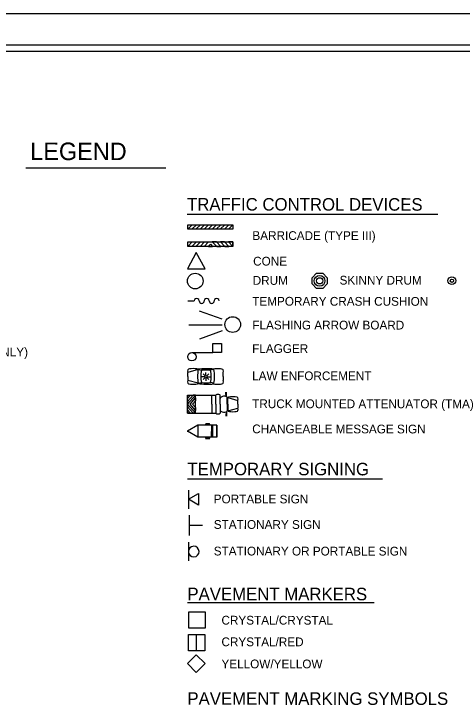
# Model space of a CAD drawing. Extents: x 0 to 1868, y 0 to 1100.
# Drawn here: x 1130 to 1488, y 547 to 1100 of the extents above; entities that cross this region are included whole.
import ezdxf

# ---------------------------------------------------------------- set-up
doc = ezdxf.new("R2010")
doc.units = 0
for name, color, linetype in [('Exist Utilities Sanitary Sewer Test Hole SUE LOS A CELL', 7, 'Continuous'), ('Exist Utilities Water Test Hole SUE LOS A CELL', 7, 'Continuous'), ('P_RDY_ROW_Permanent_Easement_CELL', 7, 'Continuous')]:
    doc.layers.add(name, color=color, linetype=linetype)

msp = doc.modelspace()

# ---------------------------------------------------------------- linework, layer by layer
at = {"layer": 'Exist Utilities Sanitary Sewer Test Hole SUE LOS A CELL'}
msp.add_lwpolyline([(0, 0), (1688, 0), (1688, 1100), (0, 1100)], close=True, dxfattribs=at)
at = {"layer": 'Exist Utilities Water Test Hole SUE LOS A CELL'}
msp.add_lwpolyline([(1275.53, 573.87), (1282.64, 580.98), (1275.53, 588.09), (1268.41, 580.98)], close=True, dxfattribs=at)
msp.add_lwpolyline([(1275.53, 573.87), (1282.64, 580.98), (1275.53, 588.09), (1268.41, 580.98)], close=True, dxfattribs=at)
at = {"layer": 'P_RDY_ROW_Permanent_Easement_CELL'}
for p, q in [((1652.71, 1075), (173.28, 1075)), ((1652.71, 1070), (740.76, 1070)), ((1139.64, 977.12), (1251.2, 977.12)), ((1268.12, 940.04), (1468.35, 940.04)), ((1268.79, 927.97), (1268.79, 931.58)), ((1268.79, 931.58), (1272.33, 931.58)), ((1272.33, 931.58), (1268.79, 927.97)), ((1268.79, 931.58), (1304.77, 931.58)), ((1268.79, 928.03), (1268.79, 931.58)), ((1272.03, 927.97), (1275.57, 931.58)), ((1278.81, 931.58), (1275.27, 927.97)), ((1275.57, 931.58), (1278.81, 931.58)), ((1278.5, 927.97), (1282.05, 931.58)), ((1285.29, 931.58), (1281.74, 927.97)), ((1282.05, 931.58), (1285.29, 931.58)), ((1284.98, 927.97), (1288.52, 931.58)), ((1291.76, 931.58), (1288.22, 927.97)), ((1288.52, 931.58), (1291.76, 931.58)), ((1291.45, 927.97), (1295.06, 931.58)), ((1298.3, 931.58), (1294.69, 927.97)), ((1295.06, 931.58), (1298.3, 931.58)), ((1297.93, 927.97), (1301.53, 931.58)), ((1304.77, 931.58), (1301.17, 927.97)), ((1301.53, 931.58), (1304.77, 931.58)), ((1304.77, 931.58), (1304.77, 928.03)), ((1304.77, 928.03), (1268.79, 928.03)), ((1275.27, 927.97), (1272.03, 927.97)), ((1281.74, 927.97), (1278.5, 927.97)), ((1288.22, 927.97), (1284.98, 927.97)), ((1294.69, 927.97), (1291.45, 927.97)), ((1301.17, 927.97), (1297.93, 927.97)), ((1268.8, 914.26), (1268.8, 917.86)), ((1268.8, 917.86), (1272.34, 917.86)), ((1272.34, 917.86), (1268.8, 914.26)), ((1268.8, 917.86), (1304.77, 917.86)), ((1268.8, 914.26), (1268.8, 917.86)), ((1304.77, 914.26), (1268.8, 914.26)), ((1272.03, 914.26), (1275.58, 917.86)), ((1275.27, 914.26), (1272.03, 914.26)), ((1278.81, 917.86), (1275.27, 914.26)), ((1275.58, 917.86), (1278.81, 917.86)), ((1278.51, 914.26), (1282.05, 917.86)), ((1281.75, 914.26), (1278.51, 914.26)), ((1285.29, 917.86), (1281.75, 914.26)), ((1282.05, 917.86), (1285.29, 917.86)), ((1284.98, 914.26), (1286.78, 916.09)), ((1288.22, 914.26), (1284.98, 914.26)), ((1285.35, 914.26), (1288.59, 914.26)), ((1286.78, 916.09), (1288.59, 914.26)), ((1291.52, 917.86), (1288.28, 917.86)), ((1288.28, 917.86), (1291.82, 914.26)), ((1295.06, 914.26), (1291.52, 917.86)), ((1291.82, 914.26), (1295.06, 914.26)), ((1297.99, 917.86), (1294.76, 917.86)), ((1294.76, 917.86), (1298.3, 914.26)), ((1301.53, 914.26), (1297.99, 917.86)), ((1298.3, 914.26), (1301.53, 914.26)), ((1304.77, 917.86), (1301.23, 917.86)), ((1301.23, 917.86), (1304.77, 914.26)), ((1304.77, 917.86), (1304.77, 914.26)), ((1304.77, 914.26), (1304.77, 917.86)), ((1268.84, 870.75), (1273.84, 870.75)), ((1296.09, 856.03), (1278.05, 862.61)), ((1296.09, 851.42), (1269.54, 851.44)), ((1296.09, 846.82), (1278.04, 840.26)), ((1272.02, 829.53), (1288.7, 829.52)), ((1277.1, 815.82), (1268.88, 813.58)), ((1268.88, 810.37), (1268.88, 813.58)), ((1277.1, 815.82), (1279.64, 815.27)), ((1283.24, 811.45), (1283.24, 813.47)), ((1289.52, 815.81), (1286.97, 815.26)), ((1288.79, 815.96), (1288.79, 815.66)), ((1296.98, 810.35), (1296.99, 813.56)), ((1268.88, 810.37), (1268.88, 807.14)), ((1281.94, 810.16), (1279.92, 810.16)), ((1282.32, 809.24), (1280.89, 807.82)), ((1282.32, 811.07), (1280.9, 812.5)), ((1283.23, 808.86), (1283.23, 806.84)), ((1284.15, 811.06), (1285.58, 812.49)), ((1284.15, 809.23), (1285.57, 807.81)), ((1284.53, 810.15), (1286.55, 810.15)), ((1296.98, 810.35), (1296.98, 807.12)), ((1277.09, 804.88), (1268.88, 807.14)), ((1277.09, 804.88), (1279.64, 805.43)), ((1289.51, 804.87), (1286.97, 805.42)), ((1288.79, 805.05), (1288.79, 804.74)), ((1288.79, 805.05), (1288.79, 804.74)), ((1299.11, 795.91), (1299.11, 797.71)), ((1299.41, 794.19), (1299.41, 797.71)), ((1299.64, 794.19), (1299.64, 797.71)), ((1268.5, 780.93), (1268.51, 795.48)), ((1268.51, 795.48), (1291.01, 795.47)), ((1268.51, 795.48), (1268.51, 792.71)), ((1268.51, 795.48), (1270.99, 795.48)), ((1270.99, 795.48), (1268.51, 792.71)), ((1268.51, 790.46), (1273.01, 795.48)), ((1274.96, 795.48), (1268.51, 788.21)), ((1270.53, 788.21), (1274.96, 793.23)), ((1274.96, 790.98), (1272.48, 788.21)), ((1273.01, 795.48), (1274.96, 795.48)), ((1274.95, 780.93), (1274.96, 795.48)), ((1274.96, 793.23), (1274.96, 790.98)), ((1287.93, 788.19), (1287.94, 795.47)), ((1291.01, 788.19), (1291.01, 795.47)), ((1294.46, 788.19), (1294.46, 795.46)), ((1300.23, 788.19), (1300.24, 793.44)), ((1300.76, 793.43), (1308.63, 791.26)), ((1300.76, 788.19), (1300.76, 793.43)), ((1308.63, 788.18), (1308.63, 791.26)), ((1268.5, 786.03), (1268.51, 788.21)), ((1273, 780.93), (1268.5, 786.03)), ((1268.51, 788.21), (1268.51, 790.46)), ((1268.51, 788.21), (1274.95, 780.93)), ((1274.95, 783.25), (1270.53, 788.21)), ((1272.56, 788.21), (1274.95, 785.5)), ((1274.95, 785.5), (1274.95, 783.25)), ((1287.93, 788.19), (1287.93, 780.92)), ((1291.01, 788.19), (1291, 780.92)), ((1294.46, 788.19), (1294.45, 780.92)), ((1300.23, 788.19), (1300.23, 782.94)), ((1300.76, 788.19), (1300.75, 782.94)), ((1308.63, 788.18), (1308.63, 785.1)), ((1268.5, 783.71), (1268.5, 780.93)), ((1270.98, 780.93), (1268.5, 783.71)), ((1268.5, 780.93), (1291, 780.92)), ((1268.5, 780.93), (1270.98, 780.93)), ((1274.95, 780.93), (1273, 780.93)), ((1299.1, 780.46), (1299.1, 778.74)), ((1299.4, 782.19), (1299.4, 778.74)), ((1299.63, 782.19), (1299.62, 778.74)), ((1300.75, 782.94), (1308.63, 785.1)), ((1276.82, 771.47), (1268.41, 766.63)), ((1291.85, 771.46), (1276.82, 771.47)), ((1276.82, 771.47), (1276.82, 761.77)), ((1286.17, 772.54), (1283.07, 772.55)), ((1286.17, 771.66), (1283.07, 771.66)), ((1287.53, 771.47), (1287.52, 761.76)), ((1288.34, 771.47), (1288.33, 761.76)), ((1291.85, 771.47), (1291.84, 761.76)), ((1291.84, 761.75), (1291.85, 771.46)), ((1276.82, 761.77), (1268.41, 766.63)), ((1291.84, 761.76), (1276.82, 761.77)), ((1286.17, 761.46), (1283.06, 761.46)), ((1286.16, 760.54), (1283.06, 760.54)), ((1268.45, 728.59), (1424.13, 728.59)), ((1269.24, 719.49), (1269.23, 704.64)), ((1269.24, 712.22), (1277.34, 716.86)), ((1277.34, 716.86), (1277.33, 707.56)), ((1277.33, 707.56), (1269.24, 712.22)), ((1269.86, 699.63), (1269.85, 683.43)), ((1269.86, 691.46), (1280.35, 691.46)), ((1269.23, 677.89), (1269.22, 663.04)), ((1268.45, 629.71), (1417.53, 629.71))]:
    msp.add_line(p, q, dxfattribs=at)
for points in [[(1275.54, 909.31), (1268.55, 896.34), (1282.64, 896.39)], [(1367.88, 884.24), (1367.88, 889.22), (1371.41, 892.74), (1376.39, 892.73), (1379.9, 889.2), (1379.9, 884.22), (1376.37, 880.7), (1371.39, 880.71)], [(1288.7, 829.52), (1288.7, 836.78), (1295.66, 836.78), (1295.66, 829.52)], [(1273.01, 795.48), (1268.51, 790.46), (1268.5, 786.03), (1273, 780.93), (1274.95, 780.93), (1268.51, 788.21), (1274.96, 795.48)], [(1268.51, 792.71), (1268.51, 795.48), (1270.99, 795.48)], [(1274.95, 783.25), (1270.53, 788.21), (1274.96, 793.23), (1274.96, 790.98), (1272.56, 788.21), (1274.95, 785.5)], [(1268.5, 783.71), (1270.98, 780.93), (1268.5, 780.93)], [(1275.81, 604.25), (1282.32, 604.25), (1282.32, 591.25), (1275.81, 591.26)], [(1275.53, 573.87), (1268.41, 580.98), (1275.53, 588.09), (1282.64, 580.98)]]:
    msp.add_lwpolyline(points, close=True, dxfattribs=at)
for points in [[(1269.48, 622.39), (1282.48, 622.38), (1282.48, 609.39), (1269.48, 609.39), (1269.48, 622.39)], [(1269.32, 604.25), (1282.32, 604.25), (1282.32, 591.25), (1269.32, 591.25), (1269.32, 604.25)]]:
    msp.add_lwpolyline(points, dxfattribs=at)
for centre, radius in [((1274.69, 886.57), 6.25), ((1373.89, 886.72), 4.31), ((1373.89, 886.72), 2.5), ((1479.45, 886.83), 3.13), ((1479.45, 886.83), 1.33), ((1304.58, 851.84), 6.25), ((1272.02, 826.14), 3.37), ((1283.24, 810.15), 1.01), ((1268.33, 766.64), 0.0857)]:
    msp.add_circle(centre, radius, dxfattribs=at)
for centre, radius, start, end in [((1275.84, 870.75), 2, 359.9598, 179.9598), ((1279.84, 870.74), 2, 179.9598, 359.9598), ((1283.84, 870.74), 2, 359.9598, 179.9598), ((1287.84, 870.74), 2, 179.9598, 359.9598), ((1291.84, 870.73), 2, 359.9598, 179.9598), ((1270.91, 814.64), 2.28, 151.8399, 208.0797), ((1302.46, 810.33), 25.94, 167.7922, 192.1274), ((1284.14, 752.81), 63.71, 85.1127, 96.5547), ((1302.46, 810.33), 23.34, 167.7922, 192.1274), ((1283.28, 763.9), 51.49, 85.8778, 94.0418), ((1264.16, 810.36), 23.34, 347.7922, 12.1274), ((1264.16, 810.36), 25.94, 347.7922, 12.1274), ((1294.96, 814.62), 2.28, 331.8399, 28.0797), ((1270.9, 806.06), 2.28, 151.8399, 208.0797), ((1284.22, 867.9), 63.71, 263.3649, 274.6973), ((1283.34, 859.19), 53.89, 266.0598, 273.8598), ((1294.96, 806.05), 2.28, 331.8399, 28.0797), ((1306.69, 792.31), 2.18, 331.8399, 28.0797), ((1306.69, 784.07), 2.18, 331.8399, 28.0797), ((1283.64, 772.1), 0.716, 142.0481, 217.8715), ((1285.61, 772.1), 0.716, 322.0481, 37.8715), ((1283.63, 761.02), 0.716, 142.0481, 217.8715), ((1285.6, 761.02), 0.716, 322.0481, 37.8715), ((1273.5, 670.46), 4.28, 182.9426, 179.7758)]:
    msp.add_arc(centre, radius, start, end, dxfattribs=at)
for centre, major_axis, ratio, start_param, end_param in [((1273, 815.76), (-4.1, -0.04), 0.2034, 3.141593, 6.283185), ((1292.87, 815.75), (4.1, -0.05), 0.2034, 0, 2.945373), ((1273, 804.94), (-4.1, 0.05), 0.2034, 0, 3.141593), ((1292.86, 804.93), (4.1, 0.04), 0.2034, 3.331712, 6.283185), ((1292.76, 795.47), (1.73, 0), 0.269913, 0, 3.141593), ((1297.38, 793.08), (2.89, 0.36), 0.503092, 0, 3.141593), ((1304.68, 793.39), (3.94, -0.05), 0.2034, 0, 3.141593), ((1292.75, 780.93), (1.73, 0), 0.269913, 3.141593, 6.283185), ((1297.37, 783.32), (2.89, -0.36), 0.503092, 3.141593, 6.283185), ((1304.68, 783), (3.94, 0.04), 0.2034, 3.141593, 6.283185)]:
    msp.add_ellipse(centre, major_axis=major_axis, ratio=ratio, start_param=start_param, end_param=end_param, dxfattribs=at)

# ---------------------------------------------------------------- texts
for s, height, p in [('LEGEND', 13.999, (1143.01, 983.2)), ('TRAFFIC CONTROL DEVICES', 10, (1268.12, 942.89)), ('BARRICADE (TYPE III)', 7, (1320.31, 919.38)), ('CONE', 7, (1320.88, 898.93)), ('DRUM', 7, (1320.55, 883.58)), ('SKINNY DRUM', 7, (1389.87, 883.73)), ('TEMPORARY CRASH CUSHION', 7, (1320.17, 866.92)), ('FLASHING ARROW BOARD', 7, (1320.26, 847.94)), ('FLAGGER', 7, (1320.1, 829.11)), ('TEMP. SHORING (LOCATION PURPOSES ONLY)', 7, (926.97, 826.53)), ('LAW ENFORCEMENT', 7, (1320.11, 807.38)), ('TRUCK MOUNTED ATTENUATOR (TMA)', 7, (1320.13, 785.06)), ('CHANGEABLE MESSAGE SIGN', 7, (1320.15, 764.95)), ('TEMPORARY SIGNING', 10, (1268.45, 731.45)), ('PORTABLE SIGN', 7, (1289.45, 709)), ('STATIONARY SIGN', 7, (1289.47, 688.62)), ('STATIONARY OR PORTABLE SIGN', 7, (1289.45, 667.39)), ('PAVEMENT MARKERS', 10, (1268.45, 631.64)), ('CRYSTAL/CRYSTAL', 7, (1295.62, 612.16)), ('CRYSTAL/RED', 7, (1295.6, 594.89)), ('YELLOW/YELLOW', 7, (1295.61, 577.24)), ('PAVEMENT MARKING SYMBOLS', 10, (1268.45, 548.11))]:
    msp.add_text(s, height=height, rotation=359.9598, dxfattribs=at).set_placement(p)

doc.saveas('drawing.dxf')
